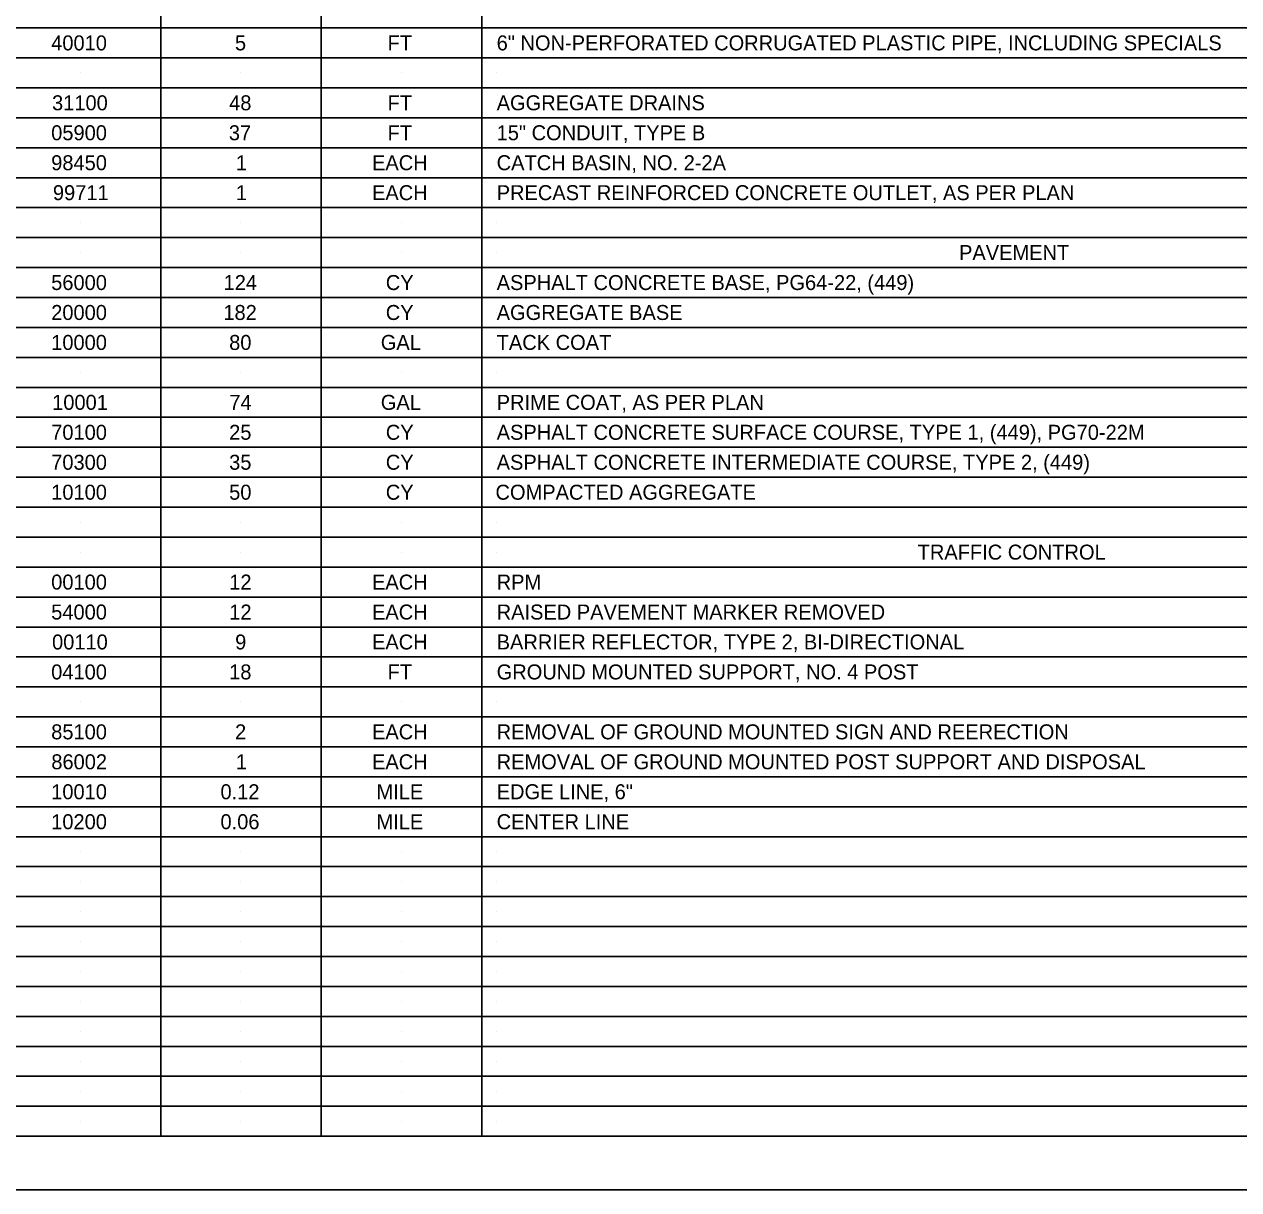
# Model space of a CAD drawing. Extents: x 0 to 34, y 0 to 22.
# Drawn here: x 16.73 to 28.07, y 0 to 10.89 of the extents above; entities that cross this region are included whole.
import ezdxf

# ---------------------------------------------------------------- set-up
doc = ezdxf.new("R2010")
doc.units = 0
for name, color, linetype in [('RD_P_RR_2', 7, 'Continuous'), ('RD_P_Text', 7, 'Continuous'), ('SC_Scratch1', 7, 'Continuous'), ('SH_Border', 7, 'Continuous'), ('SH_Cut_Line', 7, 'Continuous'), ('SH_Data', 7, 'Continuous')]:
    doc.layers.add(name, color=color, linetype=linetype)

msp = doc.modelspace()

# ---------------------------------------------------------------- linework, layer by layer
at = {"layer": 'SC_Scratch1'}
for p, q in [((17.25, 10.72), (17.25, 10.72)), ((18.75, 10.72), (18.75, 10.72)), ((20.25, 10.72), (20.25, 10.72)), ((21.14, 10.72), (21.14, 10.72)), ((17.25, 10.44), (17.25, 10.44)), ((18.75, 10.44), (18.75, 10.44)), ((20.25, 10.44), (20.25, 10.44)), ((21.14, 10.44), (21.14, 10.44)), ((17.25, 10.16), (17.25, 10.16)), ((18.75, 10.16), (18.75, 10.16)), ((20.25, 10.16), (20.25, 10.16)), ((21.14, 10.16), (21.14, 10.16)), ((17.25, 9.88), (17.25, 9.88)), ((18.75, 9.88), (18.75, 9.88)), ((20.25, 9.88), (20.25, 9.88)), ((21.14, 9.88), (21.14, 9.88)), ((17.25, 9.6), (17.25, 9.6)), ((18.75, 9.6), (18.75, 9.6)), ((20.25, 9.6), (20.25, 9.6)), ((21.14, 9.6), (21.14, 9.6)), ((17.25, 9.32), (17.25, 9.32)), ((18.75, 9.32), (18.75, 9.32)), ((20.25, 9.32), (20.25, 9.32)), ((21.14, 9.32), (21.14, 9.32)), ((17.25, 9.04), (17.25, 9.04)), ((18.75, 9.04), (18.75, 9.04)), ((20.25, 9.04), (20.25, 9.04)), ((21.14, 9.04), (21.14, 9.04)), ((17.25, 8.76), (17.25, 8.76)), ((18.75, 8.76), (18.75, 8.76)), ((20.25, 8.76), (20.25, 8.76)), ((21.14, 8.76), (21.14, 8.76)), ((17.25, 8.48), (17.25, 8.48)), ((18.75, 8.48), (18.75, 8.48)), ((20.25, 8.48), (20.25, 8.48)), ((21.14, 8.48), (21.14, 8.48)), ((17.25, 8.2), (17.25, 8.2)), ((18.75, 8.2), (18.75, 8.2)), ((20.25, 8.2), (20.25, 8.2)), ((21.14, 8.2), (21.14, 8.2)), ((17.25, 7.92), (17.25, 7.92)), ((18.75, 7.92), (18.75, 7.92)), ((20.25, 7.92), (20.25, 7.92)), ((21.14, 7.92), (21.14, 7.92)), ((17.25, 7.64), (17.25, 7.64)), ((18.75, 7.64), (18.75, 7.64)), ((20.25, 7.64), (20.25, 7.64)), ((21.14, 7.64), (21.14, 7.64)), ((17.25, 7.36), (17.25, 7.36)), ((18.75, 7.36), (18.75, 7.36)), ((20.25, 7.36), (20.25, 7.36)), ((21.14, 7.36), (21.14, 7.36)), ((17.25, 7.08), (17.25, 7.08)), ((18.75, 7.08), (18.75, 7.08)), ((20.25, 7.08), (20.25, 7.08)), ((21.14, 7.08), (21.14, 7.08)), ((17.25, 6.8), (17.25, 6.8)), ((18.75, 6.8), (18.75, 6.8)), ((20.25, 6.8), (20.25, 6.8)), ((21.14, 6.8), (21.14, 6.8)), ((17.25, 6.52), (17.25, 6.52)), ((18.75, 6.52), (18.75, 6.52)), ((20.25, 6.52), (20.25, 6.52)), ((21.14, 6.52), (21.14, 6.52)), ((17.25, 6.24), (17.25, 6.24)), ((18.75, 6.24), (18.75, 6.24)), ((20.25, 6.24), (20.25, 6.24)), ((21.14, 6.24), (21.14, 6.24)), ((17.25, 5.96), (17.25, 5.96)), ((18.75, 5.96), (18.75, 5.96)), ((20.25, 5.96), (20.25, 5.96)), ((21.14, 5.96), (21.14, 5.96)), ((17.25, 5.68), (17.25, 5.68)), ((18.75, 5.68), (18.75, 5.68)), ((20.25, 5.68), (20.25, 5.68)), ((21.14, 5.68), (21.14, 5.68)), ((17.25, 5.4), (17.25, 5.4)), ((18.75, 5.4), (18.75, 5.4)), ((20.25, 5.4), (20.25, 5.4)), ((21.14, 5.4), (21.14, 5.4)), ((17.25, 5.12), (17.25, 5.12)), ((18.75, 5.12), (18.75, 5.12)), ((20.25, 5.12), (20.25, 5.12)), ((21.14, 5.12), (21.14, 5.12)), ((17.25, 4.84), (17.25, 4.84)), ((18.75, 4.84), (18.75, 4.84)), ((20.25, 4.84), (20.25, 4.84)), ((21.14, 4.84), (21.14, 4.84)), ((17.25, 4.56), (17.25, 4.56)), ((18.75, 4.56), (18.75, 4.56)), ((20.25, 4.56), (20.25, 4.56)), ((21.14, 4.56), (21.14, 4.56)), ((17.25, 4.28), (17.25, 4.28)), ((18.75, 4.28), (18.75, 4.28)), ((20.25, 4.28), (20.25, 4.28)), ((21.14, 4.28), (21.14, 4.28)), ((17.25, 4), (17.25, 4)), ((18.75, 4), (18.75, 4)), ((20.25, 4), (20.25, 4)), ((21.14, 4), (21.14, 4)), ((17.25, 3.72), (17.25, 3.72)), ((18.75, 3.72), (18.75, 3.72)), ((20.25, 3.72), (20.25, 3.72)), ((21.14, 3.72), (21.14, 3.72)), ((17.25, 3.44), (17.25, 3.44)), ((18.75, 3.44), (18.75, 3.44)), ((20.25, 3.44), (20.25, 3.44)), ((21.14, 3.44), (21.14, 3.44)), ((17.25, 3.16), (17.25, 3.16)), ((18.75, 3.16), (18.75, 3.16)), ((20.25, 3.16), (20.25, 3.16)), ((21.14, 3.16), (21.14, 3.16)), ((17.25, 2.88), (17.25, 2.88)), ((18.75, 2.88), (18.75, 2.88)), ((20.25, 2.88), (20.25, 2.88)), ((21.14, 2.88), (21.14, 2.88)), ((17.25, 2.6), (17.25, 2.6)), ((18.75, 2.6), (18.75, 2.6)), ((20.25, 2.6), (20.25, 2.6)), ((21.14, 2.6), (21.14, 2.6)), ((17.25, 2.32), (17.25, 2.32)), ((18.75, 2.32), (18.75, 2.32)), ((20.25, 2.32), (20.25, 2.32)), ((21.14, 2.32), (21.14, 2.32)), ((17.25, 2.04), (17.25, 2.04)), ((18.75, 2.04), (18.75, 2.04)), ((20.25, 2.04), (20.25, 2.04)), ((21.14, 2.04), (21.14, 2.04)), ((17.25, 1.76), (17.25, 1.76)), ((18.75, 1.76), (18.75, 1.76)), ((20.25, 1.76), (20.25, 1.76)), ((21.14, 1.76), (21.14, 1.76)), ((17.25, 1.48), (17.25, 1.48)), ((18.75, 1.48), (18.75, 1.48)), ((20.25, 1.48), (20.25, 1.48)), ((21.14, 1.48), (21.14, 1.48)), ((17.25, 1.2), (17.25, 1.2)), ((18.75, 1.2), (18.75, 1.2)), ((20.25, 1.2), (20.25, 1.2)), ((21.14, 1.2), (21.14, 1.2)), ((17.25, 0.92), (17.25, 0.92)), ((18.75, 0.92), (18.75, 0.92)), ((20.25, 0.92), (20.25, 0.92)), ((21.14, 0.92), (21.14, 0.92)), ((17.25, 0.64), (17.25, 0.64)), ((18.75, 0.64), (18.75, 0.64)), ((20.25, 0.64), (20.25, 0.64)), ((21.14, 0.64), (21.14, 0.64))]:
    msp.add_line(p, q, dxfattribs=at)
at = {"layer": 'SH_Border'}
msp.add_lwpolyline([(1.5, 21.5), (33.5, 21.5), (33.5, 0.5), (1.5, 0.5)], close=True, dxfattribs=at)
at = {"layer": 'SH_Cut_Line'}
msp.add_lwpolyline([(0, 0), (34, 0), (34, 22), (0, 22)], close=True, dxfattribs=at)
at = {"layer": 'SH_Data'}
for p, q in [((18, 21.5), (18, 0.5)), ((19.5, 21.5), (19.5, 0.5)), ((21, 21.5), (21, 0.5)), ((32, 10.86), (1.5, 10.86)), ((32, 10.58), (1.5, 10.58)), ((32, 10.3), (1.5, 10.3)), ((32, 10.02), (1.5, 10.02)), ((32, 9.74), (1.5, 9.74)), ((32, 9.46), (1.5, 9.46)), ((32, 9.18), (1.5, 9.18)), ((32, 8.9), (1.5, 8.9)), ((32, 8.62), (1.5, 8.62)), ((32, 8.34), (1.5, 8.34)), ((32, 8.06), (1.5, 8.06)), ((32, 7.78), (1.5, 7.78)), ((32, 7.5), (1.5, 7.5)), ((32, 7.22), (1.5, 7.22)), ((32, 6.94), (1.5, 6.94)), ((32, 6.66), (1.5, 6.66)), ((32, 6.38), (1.5, 6.38)), ((32, 6.1), (1.5, 6.1)), ((32, 5.82), (1.5, 5.82)), ((32, 5.54), (1.5, 5.54)), ((32, 5.26), (1.5, 5.26)), ((32, 4.98), (1.5, 4.98)), ((32, 4.7), (1.5, 4.7)), ((32, 4.42), (1.5, 4.42)), ((32, 4.14), (1.5, 4.14)), ((32, 3.86), (1.5, 3.86)), ((32, 3.58), (1.5, 3.58)), ((32, 3.3), (1.5, 3.3)), ((32, 3.02), (1.5, 3.02)), ((32, 2.74), (1.5, 2.74)), ((32, 2.46), (1.5, 2.46)), ((32, 2.18), (1.5, 2.18)), ((32, 1.9), (1.5, 1.9)), ((32, 1.62), (1.5, 1.62)), ((32, 1.34), (1.5, 1.34)), ((32, 1.06), (1.5, 1.06)), ((32, 0.78), (1.5, 0.78))]:
    msp.add_line(p, q, dxfattribs=at)

# ---------------------------------------------------------------- texts
at = {"layer": 'RD_P_RR_2'}
for s, p in [('10100', (16.977, 6.45)), ('50', (18.64, 6.45)), ('CY', (20.104, 6.45)), ('COMPACTED AGGREGATE', (21.129, 6.45))]:
    msp.add_text(s, height=0.14, dxfattribs=at).set_placement(p)
at = {"layer": 'RD_P_Text'}
for s, p in [('40010', (16.977, 10.65)), ('5', (18.694, 10.65)), ('FT', (20.121, 10.65)), ('6" NON-PERFORATED CORRUGATED PLASTIC PIPE, INCLUDING SPECIALS', (21.14, 10.65)), ('31100', (16.985, 10.09)), ('48', (18.64, 10.09)), ('FT', (20.121, 10.09)), ('AGGREGATE DRAINS', (21.14, 10.09)), ('05900', (16.977, 9.81)), ('37', (18.637, 9.81)), ('FT', (20.121, 9.81)), ('15" CONDUIT, TYPE B', (21.14, 9.81)), ('98450', (16.977, 9.53)), ('1', (18.703, 9.53)), ('EACH', (19.975, 9.53)), ('CATCH BASIN, NO. 2-2A', (21.14, 9.53)), ('99711', (16.993, 9.25)), ('1', (18.703, 9.25)), ('EACH', (19.975, 9.25)), ('PRECAST REINFORCED CONCRETE OUTLET, AS PER PLAN', (21.14, 9.25)), ('PAVEMENT', (25.461, 8.69)), ('56000', (16.977, 8.41)), ('124', (18.588, 8.41)), ('CY', (20.104, 8.41)), ('ASPHALT CONCRETE BASE, PG64-22, (449)', (21.14, 8.41)), ('20000', (16.977, 8.13)), ('182', (18.586, 8.13)), ('CY', (20.104, 8.13)), ('AGGREGATE BASE', (21.14, 8.13)), ('10000', (16.977, 7.85)), ('80', (18.64, 7.85)), ('GAL', (20.057, 7.85)), ('TACK COAT', (21.14, 7.85)), ('10001', (16.986, 7.29)), ('74', (18.642, 7.29)), ('GAL', (20.057, 7.29)), ('PRIME COAT, AS PER PLAN', (21.14, 7.29)), ('70100', (16.977, 7.01)), ('25', (18.64, 7.01)), ('CY', (20.104, 7.01)), ('ASPHALT CONCRETE SURFACE COURSE, TYPE 1, (449), PG70-22M', (21.14, 7.01)), ('70300', (16.977, 6.73)), ('35', (18.64, 6.73)), ('CY', (20.104, 6.73)), ('ASPHALT CONCRETE INTERMEDIATE COURSE, TYPE 2, (449)', (21.14, 6.73)), ('TRAFFIC CONTROL', (25.074, 5.89)), ('00100', (16.977, 5.61)), ('12', (18.641, 5.61)), ('EACH', (19.975, 5.61)), ('RPM', (21.14, 5.61)), ('54000', (16.977, 5.33)), ('12', (18.641, 5.33)), ('EACH', (19.975, 5.33)), ('RAISED PAVEMENT MARKER REMOVED', (21.14, 5.33)), ('00110', (16.985, 5.05)), ('9', (18.696, 5.05)), ('EACH', (19.975, 5.05)), ('BARRIER REFLECTOR, TYPE 2, BI-DIRECTIONAL', (21.14, 5.05)), ('04100', (16.977, 4.77)), ('18', (18.64, 4.77)), ('FT', (20.121, 4.77)), ('GROUND MOUNTED SUPPORT, NO. 4 POST', (21.14, 4.77)), ('85100', (16.977, 4.21)), ('2', (18.695, 4.21)), ('EACH', (19.975, 4.21)), ('REMOVAL OF GROUND MOUNTED SIGN AND REERECTION', (21.14, 4.21)), ('86002', (16.978, 3.93)), ('1', (18.703, 3.93)), ('EACH', (19.975, 3.93)), ('REMOVAL OF GROUND MOUNTED POST SUPPORT AND DISPOSAL', (21.14, 3.93)), ('10010', (16.977, 3.65)), ('0.12', (18.559, 3.65)), ('MILE', (20.017, 3.65)), ('EDGE LINE, 6"', (21.14, 3.65)), ('10200', (16.977, 3.37)), ('0.06', (18.559, 3.37)), ('MILE', (20.017, 3.37)), ('CENTER LINE', (21.14, 3.37))]:
    msp.add_text(s, height=0.14, dxfattribs=at).set_placement(p)

doc.saveas('drawing.dxf')
